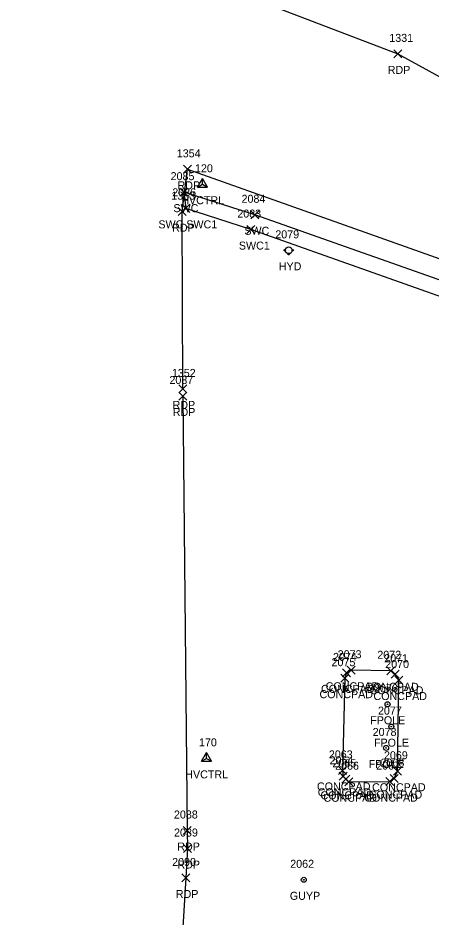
# Model space of a CAD drawing. Extents: x 1767353 to 1772625, y 740790 to 747702.
# Drawn here: x 1770045.2 to 1770148.4, y 741766 to 741990.7 of the extents above; entities that cross this region are included whole.
import ezdxf

# ---------------------------------------------------------------- set-up
doc = ezdxf.new("R2010")
doc.units = 0
for name, color, linetype in [('C_A', 7, 'Continuous'), ('C_I', 7, 'Continuous'), ('CPSM', 7, 'Continuous'), ('L_A', 7, 'Continuous'), ('L_I', 7, 'Continuous'), ('L_TIC', 7, 'Continuous'), ('LFP', 7, 'Continuous'), ('LS', 7, 'Continuous'), ('P_A', 7, 'Continuous'), ('P_I', 7, 'Continuous'), ('P_TIC', 7, 'Continuous'), ('PET', 7, 'Continuous'), ('R_A', 7, 'Continuous'), ('R_I', 7, 'Continuous'), ('R_TIC', 7, 'Continuous'), ('RSW', 7, 'Continuous'), ('U_A', 7, 'Continuous'), ('U_I', 7, 'Continuous'), ('UPGW', 7, 'Continuous'), ('UWFH', 7, 'Continuous')]:
    doc.layers.add(name, color=color, linetype=linetype)

msp = doc.modelspace()

# ---------------------------------------------------------------- linework, layer by layer
at = {"layer": 'CPSM'}
for p, q in [((1770090.04, 741948.42), (1770091.29, 741950.59)), ((1770090.04, 741948.42), (1770091.29, 741950.59)), ((1770090.04, 741948.42), (1770091.29, 741950.59)), ((1770090.04, 741948.42), (1770091.29, 741950.59)), ((1770090.04, 741948.42), (1770091.29, 741950.59)), ((1770090.04, 741948.42), (1770091.29, 741949.15)), ((1770090.04, 741948.42), (1770091.29, 741949.15)), ((1770090.04, 741948.42), (1770091.29, 741949.15)), ((1770090.04, 741948.42), (1770091.29, 741949.15)), ((1770090.04, 741948.42), (1770091.29, 741949.15)), ((1770092.54, 741948.42), (1770091.29, 741950.59)), ((1770091.29, 741949.15), (1770091.29, 741950.59)), ((1770092.54, 741948.42), (1770091.29, 741950.59)), ((1770091.29, 741949.15), (1770091.29, 741950.59)), ((1770092.54, 741948.42), (1770091.29, 741950.59)), ((1770091.29, 741949.15), (1770091.29, 741950.59)), ((1770092.54, 741948.42), (1770091.29, 741950.59)), ((1770091.29, 741949.15), (1770091.29, 741950.59)), ((1770092.54, 741948.42), (1770091.29, 741950.59)), ((1770091.29, 741949.15), (1770091.29, 741950.59)), ((1770091.29, 741949.15), (1770091.29, 741949.15)), ((1770091.29, 741949.15), (1770092.54, 741948.42)), ((1770091.29, 741949.15), (1770091.29, 741949.15)), ((1770091.29, 741949.15), (1770092.54, 741948.42)), ((1770091.29, 741949.15), (1770091.29, 741949.15)), ((1770091.29, 741949.15), (1770092.54, 741948.42)), ((1770091.29, 741949.15), (1770091.29, 741949.15)), ((1770091.29, 741949.15), (1770092.54, 741948.42)), ((1770091.29, 741949.15), (1770091.29, 741949.15)), ((1770091.29, 741949.15), (1770092.54, 741948.42)), ((1770090.04, 741948.42), (1770092.54, 741948.42)), ((1770090.04, 741948.42), (1770092.54, 741948.42)), ((1770090.04, 741948.42), (1770092.54, 741948.42)), ((1770090.04, 741948.42), (1770092.54, 741948.42)), ((1770090.04, 741948.42), (1770092.54, 741948.42)), ((1770091.04, 741804.96), (1770092.29, 741807.12)), ((1770093.54, 741804.96), (1770092.29, 741807.12)), ((1770092.29, 741805.68), (1770092.29, 741807.12)), ((1770091.04, 741804.96), (1770092.29, 741805.68)), ((1770091.04, 741804.96), (1770093.54, 741804.96)), ((1770092.29, 741805.68), (1770092.29, 741805.68)), ((1770092.29, 741805.68), (1770093.54, 741804.96))]:
    msp.add_line(p, q, dxfattribs=at)
at = {"layer": 'L_TIC'}
for points in [[(1770126.24, 741826.04), (1770128.24, 741828.04)], [(1770128.24, 741826.04), (1770126.24, 741828.04)], [(1770127.41, 741826.7), (1770129.41, 741828.7)], [(1770129.41, 741826.7), (1770127.41, 741828.7)], [(1770137.31, 741826.57), (1770139.31, 741828.57)], [(1770139.31, 741826.57), (1770137.31, 741828.57)], [(1770138.46, 741825.71), (1770140.46, 741827.71)], [(1770140.46, 741825.71), (1770138.46, 741827.71)], [(1770125.87, 741824.72), (1770127.87, 741826.72)], [(1770127.87, 741824.72), (1770125.87, 741826.72)], [(1770125.87, 741824.72), (1770127.87, 741826.72)], [(1770127.87, 741824.72), (1770125.87, 741826.72)], [(1770139.37, 741824.25), (1770141.37, 741826.25)], [(1770141.37, 741824.25), (1770139.37, 741826.25)], [(1770125.25, 741801.67), (1770127.25, 741803.67)], [(1770127.25, 741801.67), (1770125.25, 741803.67)], [(1770125.25, 741801.67), (1770127.25, 741803.67)], [(1770127.25, 741801.67), (1770125.25, 741803.67)], [(1770139.03, 741801.46), (1770141.03, 741803.46)], [(1770141.03, 741801.46), (1770139.03, 741803.46)], [(1770125.44, 741800.21), (1770127.44, 741802.21)], [(1770127.44, 741800.21), (1770125.44, 741802.21)], [(1770126.12, 741799.45), (1770128.12, 741801.45)], [(1770128.12, 741799.45), (1770126.12, 741801.45)], [(1770126.87, 741798.84), (1770128.87, 741800.84)], [(1770128.87, 741798.84), (1770126.87, 741800.84)], [(1770137.09, 741798.87), (1770139.09, 741800.87)], [(1770139.09, 741798.87), (1770137.09, 741800.87)], [(1770138.16, 741799.61), (1770140.16, 741801.61)], [(1770140.16, 741799.61), (1770138.16, 741801.61)]]:
    msp.add_lwpolyline(points, dxfattribs=at)
at = {"layer": 'LFP'}
for centre, radius in [((1770137.52, 741819.2), 0.625), ((1770137.52, 741819.2), 0.0833), ((1770138.47, 741813.61), 0.625), ((1770138.47, 741813.61), 0.0833), ((1770137.15, 741808.28), 0.625), ((1770137.15, 741808.28), 0.0833)]:
    msp.add_circle(centre, radius, dxfattribs=at)
at = {"layer": 'LS'}
for points in [[(1770126.25, 741802.67), (1770126.44, 741801.21), (1770127.12, 741800.45), (1770127.87, 741799.84), (1770138.09, 741799.87), (1770139.16, 741800.61), (1770140.03, 741802.46), (1770140.37, 741825.25), (1770139.46, 741826.71), (1770138.31, 741827.57), (1770128.41, 741827.7), (1770127.24, 741827.04), (1770126.87, 741825.72)], [(1770126.87, 741825.72), (1770126.25, 741802.67)]]:
    msp.add_lwpolyline(points, dxfattribs=at)
at = {"layer": 'P_TIC'}
for points in [[(1770139.08, 741980.73), (1770141.08, 741982.73)], [(1770141.08, 741980.73), (1770139.08, 741982.73)], [(1770086.55, 741951.88), (1770088.55, 741953.88)], [(1770088.55, 741951.88), (1770086.55, 741953.88)], [(1770085.19, 741941.3), (1770087.19, 741943.3)], [(1770087.19, 741941.3), (1770085.19, 741943.3)], [(1770085.33, 741897), (1770087.33, 741899)], [(1770087.33, 741897), (1770085.33, 741899)], [(1770085.36, 741895.23), (1770087.36, 741897.23)], [(1770087.36, 741895.23), (1770085.36, 741897.23)], [(1770086.49, 741786.65), (1770088.49, 741788.65)], [(1770088.49, 741786.65), (1770086.49, 741788.65)], [(1770086.53, 741782.15), (1770088.53, 741784.15)], [(1770088.53, 741782.15), (1770086.53, 741784.15)], [(1770086.13, 741774.79), (1770088.13, 741776.79)], [(1770088.13, 741774.79), (1770086.13, 741776.79)]]:
    msp.add_lwpolyline(points, dxfattribs=at)
at = {"layer": 'PET'}
for points in [[(1770097.29, 741998.16), (1770140.08, 741981.73), (1770172.76, 741963.83)], [(1770086.33, 741898), (1770086.19, 741942.3), (1770087.55, 741952.88), (1770152.01, 741929.98)], [(1770086.36, 741896.23), (1770087.49, 741787.65), (1770087.53, 741783.15), (1770087.13, 741775.79), (1770085.91, 741755.24), (1770081.77, 741704.72), (1770080.78, 741668.58), (1770077.45, 741606.56), (1770073.71, 741567.99), (1770067.82, 741517.29), (1770065.02, 741495.1), (1770064.65, 741473.85), (1770058.3, 741423.48), (1770050.58, 741368.28), (1770045.18, 741323.67)]]:
    msp.add_lwpolyline(points, dxfattribs=at)
at = {"layer": 'R_TIC'}
for points in [[(1770085.66, 741946.17), (1770087.66, 741948.17)], [(1770087.66, 741946.17), (1770085.66, 741948.17)], [(1770086.12, 741942.13), (1770088.12, 741944.13)], [(1770088.12, 741942.13), (1770086.12, 741944.13)], [(1770086.12, 741942.13), (1770088.12, 741944.13)], [(1770088.12, 741942.13), (1770086.12, 741944.13)], [(1770103.38, 741940.52), (1770105.38, 741942.52)], [(1770105.38, 741940.52), (1770103.38, 741942.52)], [(1770102.33, 741936.82), (1770104.33, 741938.82)], [(1770104.33, 741936.82), (1770102.33, 741938.82)]]:
    msp.add_lwpolyline(points, dxfattribs=at)
at = {"layer": 'RSW'}
for points in [[(1770195.74, 741909.28), (1770104.38, 741941.52), (1770086.66, 741947.17), (1770087.12, 741943.13)], [(1770195.07, 741905.38), (1770103.33, 741937.82), (1770087.12, 741943.13)]]:
    msp.add_lwpolyline(points, dxfattribs=at)
at = {"layer": 'UPGW'}
for radius in [0.625, 0.0833]:
    msp.add_circle((1770116.6, 741775.33), radius, dxfattribs=at)
at = {"layer": 'UWFH'}
msp.add_line((1770112.83, 741932.64), (1770112.83, 741932.64), dxfattribs=at)
for centre, radius in [((1770112.83, 741932.64), 0.833), ((1770111.83, 741932.64), 0.167), ((1770112.83, 741931.64), 0.167), ((1770113.83, 741932.64), 0.167)]:
    msp.add_circle(centre, radius, dxfattribs=at)

# ---------------------------------------------------------------- texts
at = {"layer": 'C_A'}
for p in [(1770085.99, 741944.15), (1770085.99, 741944.15), (1770085.99, 741944.15), (1770085.99, 741944.15), (1770085.99, 741944.15), (1770086.98, 741800.68)]:
    msp.add_text('HVCTRL', height=2, dxfattribs=at).set_placement(p)
at = {"layer": 'C_I'}
for s, p in [('120', (1770089.41, 741952.14)), ('120', (1770089.41, 741952.14)), ('120', (1770089.41, 741952.14)), ('120', (1770089.41, 741952.14)), ('120', (1770089.41, 741952.14)), ('170', (1770090.41, 741808.68))]:
    msp.add_text(s, height=2, dxfattribs=at).set_placement(p)
at = {"layer": 'L_A'}
for s, p in [('CONCPAD', (1770120.52, 741820.72)), ('CONCPAD', (1770120.52, 741820.72)), ('CONCPAD', (1770120.89, 741822.04)), ('CONCPAD', (1770122.06, 741822.7)), ('CONCPAD', (1770131.95, 741822.57)), ('CONCPAD', (1770133.11, 741821.71)), ('CONCPAD', (1770134.01, 741820.25)), ('FPOLE', (1770133.19, 741814.2)), ('FPOLE', (1770134.13, 741808.61)), ('FPOLE', (1770132.81, 741803.28)), ('CONCPAD', (1770119.89, 741797.67)), ('CONCPAD', (1770119.89, 741797.67)), ('CONCPAD', (1770120.09, 741796.21)), ('CONCPAD', (1770133.67, 741797.46)), ('CONCPAD', (1770120.77, 741795.45)), ('CONCPAD', (1770121.51, 741794.84)), ('CONCPAD', (1770131.73, 741794.87)), ('CONCPAD', (1770132.81, 741795.61))]:
    msp.add_text(s, height=2, dxfattribs=at).set_placement(p)
at = {"layer": 'L_I'}
for s, p in [('2074', (1770123.9, 741830.04)), ('2073', (1770125.07, 741830.7)), ('2072', (1770134.97, 741830.57)), ('2071', (1770136.69, 741829.71)), ('2075', (1770123.53, 741828.72)), ('2075', (1770123.53, 741828.72)), ('2070', (1770136.94, 741828.25)), ('2076', (1770134.13, 741822.2)), ('2077', (1770135.13, 741816.61)), ('2078', (1770133.81, 741811.28)), ('2063', (1770122.86, 741805.67)), ('2063', (1770122.86, 741805.67)), ('2069', (1770136.63, 741805.46)), ('2064', (1770123.05, 741804.21)), ('2065', (1770123.74, 741803.45)), ('2066', (1770124.43, 741802.84)), ('2067', (1770134.7, 741802.87)), ('2068', (1770135.78, 741803.61))]:
    msp.add_text(s, height=2, dxfattribs=at).set_placement(p)
at = {"layer": 'P_A'}
for p in [(1770137.57, 741976.73), (1770085.04, 741947.88), (1770083.68, 741937.3), (1770083.81, 741893), (1770083.85, 741891.23), (1770084.98, 741782.65), (1770085.02, 741778.15), (1770084.62, 741770.79)]:
    msp.add_text('RDP', height=2, dxfattribs=at).set_placement(p)
at = {"layer": 'P_I'}
for s, p in [('1331', (1770137.96, 741984.73)), ('1354', (1770084.86, 741955.88)), ('1353', (1770083.5, 741945.3)), ('1352', (1770083.63, 741901)), ('2087', (1770083.02, 741899.23)), ('2088', (1770084.15, 741790.65)), ('2089', (1770084.18, 741786.15)), ('2090', (1770083.7, 741778.79))]:
    msp.add_text(s, height=2, dxfattribs=at).set_placement(p)
at = {"layer": 'R_A'}
for s, p in [('SWC', (1770084.02, 741942.17)), ('SWC SWC1', (1770080.26, 741938.13)), ('SWC SWC1', (1770080.26, 741938.13)), ('SWC', (1770101.74, 741936.52)), ('SWC1', (1770100.37, 741932.82))]:
    msp.add_text(s, height=2, dxfattribs=at).set_placement(p)
at = {"layer": 'R_I'}
for s, p in [('2085', (1770083.32, 741950.17)), ('2086', (1770083.73, 741946.13)), ('2086', (1770083.73, 741946.13)), ('2084', (1770101.04, 741944.52)), ('2083', (1770099.99, 741940.82))]:
    msp.add_text(s, height=2, dxfattribs=at).set_placement(p)
at = {"layer": 'U_A'}
for s, p in [('HYD', (1770110.35, 741927.64)), ('GUYP', (1770113.11, 741770.33))]:
    msp.add_text(s, height=2, dxfattribs=at).set_placement(p)
at = {"layer": 'U_I'}
for s, p in [('2079', (1770109.48, 741935.64)), ('2062', (1770113.21, 741778.33))]:
    msp.add_text(s, height=2, dxfattribs=at).set_placement(p)

doc.saveas('drawing.dxf')
